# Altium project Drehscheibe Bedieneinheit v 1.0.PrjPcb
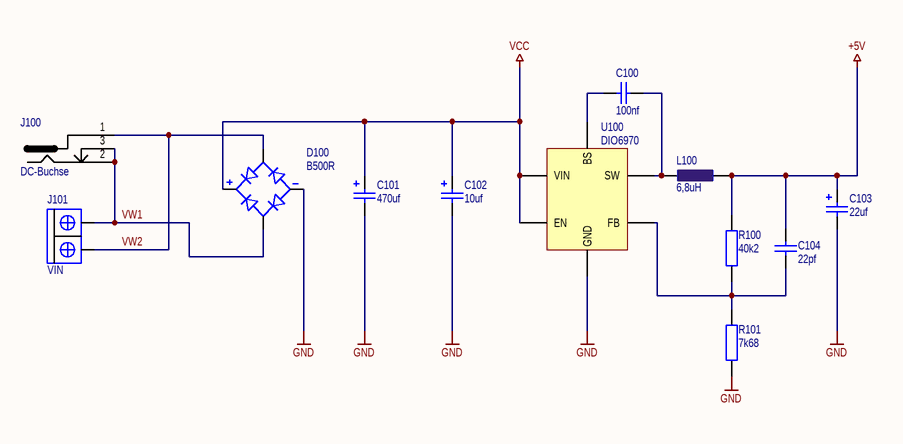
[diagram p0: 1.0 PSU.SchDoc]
City: Neustift-Innermanzing; Client: Wolfgang Paris, Gerhard Abraham; Company: PCSG; Country: Austria; Drawnby1: BRAL; Drawnby2: SONP; Email: office@pcsb.at; License: N/A; Number: 1; Phone: 02774/29452; Street: Hauptstraße 47; Title: Drehscheibe Bedieneinheit; Version: v1.0; web: www.pcsb.at; ZIP: A-3052
7 sheets, 71 parts. Net scope: global (net labels, ports and power ports of the same name join across sheets).
Board file: Bedieneinheit v1.0.PcbDoc
Sheets:
  1.0 PSU.SchDoc
  2.0 Microcontroller.SchDoc
  3.0 Display.SchDoc
  4.0 Steppermotor & Peripheral.SchDoc
  5.0 Demodulation.SchDoc
  6.0 Relais and Connector.SchDoc
  7.0 Bedieneinheit.SchDoc

## Sheet 1.0 PSU.SchDoc: Drehscheibe Bedieneinheit
size A4; SheetNumber: 1; SheetTotal: 7

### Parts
C100  100nf  [C_SMD_0805]
C101  470uf  [C_SMD_F-TYP]
C102  10uf  [C_SMD_C-TYP]
C103  22uf  [C_SMD_C-TYP]
C104  22pf  [C_SMD_0805]
D100  B500R  [D_THT_FBR-R]
J100  DC-Buchse  [J_THT_CUI_PJ-006A]
J101  VIN  [J_THT_Printklemme 2x]
L100  6,8uH  [L_SMD_BWVS00606045]
R100  40k2  [R_SMD_0805]
R101  7k68  [R_SMD_1206]
U100  DIO6970  [SOT23-6]

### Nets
+5V: C103.1 C104.1 L100.1 R100.2
GND: C101.2 C102.2 C103.2 D100.4(NEG) R101.1 U100.1(GND)
VCC: C101.1 C102.1 D100.1(POS) U100.3(VIN) U100.5(EN)
VW1: D100.3(AC2) J100.2 J100.3 J101.2
VW2: D100.2(AC1) J100.1 J101.1
NetC100_1: C100.1 U100.6(BS)
NetC100_2: C100.2 L100.2 U100.2(SW)
NetC104_2: C104.2 R100.1 R101.2 U100.4(FB)

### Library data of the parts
C100 C104 = C_SMD_KO: Kondensator SMD Universal, Keramik, Folie, usw.
C101-C103 = C_SMD_ELK: SMD Elektrolytkondensator
D100 = D_THT_Brückengleichrichter: Bruckengleichrichter
J100 = J_THT_Hohlstecker
J101 = J_THT_Printklemme 2x: Printklemme
L100 = L_SMD_Spule: Spule SMD
R100 R101 = R_SMD_Widerstand: Widerstand SMD
U100 = U_DIO6970: Buckconverter

## Sheet 2.0 Microcontroller.SchDoc: Drehscheibe Bedieneinheit
size A4; SheetNumber: 2; SheetTotal: 7
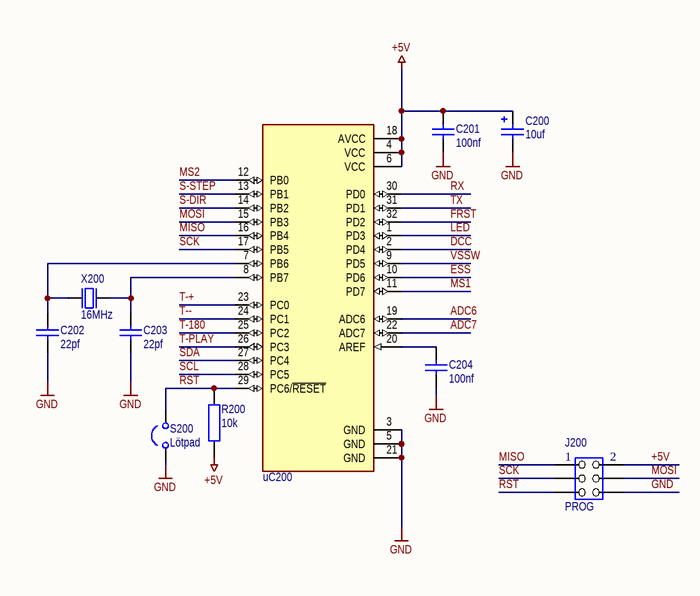
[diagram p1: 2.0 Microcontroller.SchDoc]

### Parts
C200  10uf  [C_SMD_C-TYP]
C201  100nf  [C_SMD_0805]
C202  22pf  [C_SMD_0805]
C203  22pf  [C_SMD_0805]
C204  100nf  [C_SMD_0805]
J200  PROG  [J_2x3]
R200  10k  [R_SMD_0805]
S200  Lötpad  [S_SMD_Pad-NO]
uC200  ATMega328(p)-AU  [TQFP-32]  (value not drawn)
X200  16MHz  [X_SMD_XTAL]

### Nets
+5V: C200.1 C201.1 J200.2 R200.1 uC200.4(VCC) uC200.6(VCC) uC200.18(AVCC)
GND: C200.2 C201.2 C202.2 C203.2 C204.2 J200.6 S200.1 uC200.3(GND) uC200.5(GND) uC200.21(GND)
ADC6: uC200.19(ADC6)
ADC7: uC200.22(ADC7)
DCC: uC200.2(PD4)
ESS: uC200.10(PD6)
FRST: uC200.32(PD2)
LED: uC200.1(PD3)
MISO: J200.1 uC200.16(PB4)
MOSI: J200.4 uC200.15(PB3)
MS1: uC200.11(PD7)
MS2: uC200.12(PB0)
RST: J200.5 R200.2 S200.2 uC200.29(PC6/~{RESET})
RX: uC200.30(PD0)
S-DIR: uC200.14(PB2)
S-STEP: uC200.13(PB1)
SCK: J200.3 uC200.17(PB5)
SCL: uC200.28(PC5)
SDA: uC200.27(PC4)
T-180: uC200.25(PC2)
T-+: uC200.23(PC0)
T--: uC200.24(PC1)
T-PLAY: uC200.26(PC3)
TX: uC200.31(PD1)
VSSW: uC200.9(PD5)
NetC202_1: C202.1 uC200.7(PB6) X200.1
NetC203_1: C203.1 uC200.8(PB7) X200.2
NetC204_1: C204.1 uC200.20(AREF)

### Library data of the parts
C200 = C_SMD_ELK: SMD Elektrolytkondensator
C201-C204 = C_SMD_KO: as C100 on sheet 1.0 PSU
J200 = J_THT_IDC 2x3: Stecker
R200 = R_SMD_Widerstand: Widerstand SMD
S200 = S_SMD_Jumper: Lötverbinder
uC200 = UC_ATMega328P-AU: Microcontroller
X200 = X_SMD_Quarz: Quarz SMD

## Sheet 3.0 Display.SchDoc: Drehscheibe Bedieneinheit
size A4; SheetNumber: 3; SheetTotal: 7
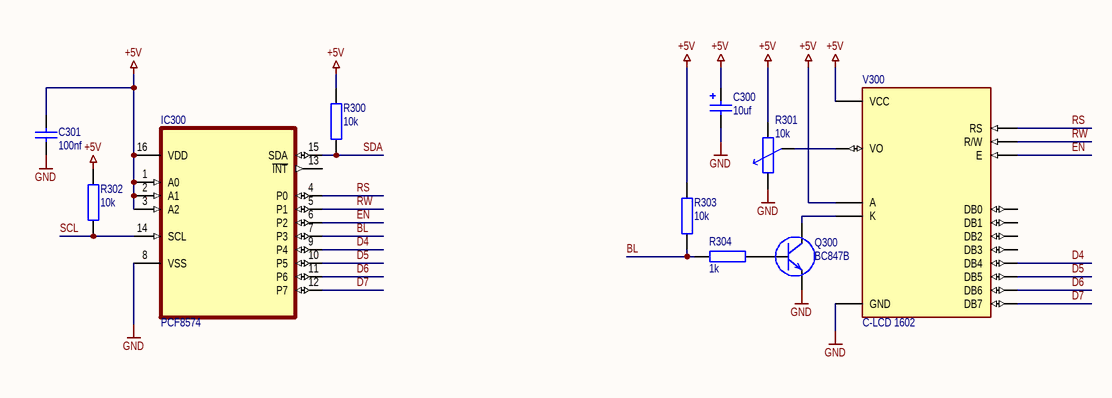
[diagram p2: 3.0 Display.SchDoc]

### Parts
C300  10uf  [C_SMD_C-TYP]
C301  100nf  [C_SMD_0805]
IC300  PCF8574  [SO-16]
Q300  BC847B  [SOT-23]
R300  10k  [R_SMD_0805]
R301  10k  [R_THT_POT-TP-.2/.1]
R302  10k  [R_SMD_0805]
R303  10k  [R_SMD_0805]
R304  1k  [R_SMD_0805]
V300  C-LCD 1602  [V_MODULE_LCD-16X2]

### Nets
+5V: C300.1 C301.1 IC300.1(A0) IC300.2(A1) IC300.3(A2) IC300.16(VDD) R300.2 R301.1 R302.2 R303.2 V300.2(VCC) V300.15(A)
GND: C300.2 C301.2 IC300.8(VSS) Q300.2(E) R301.2 V300.1(GND)
BL: IC300.7(P3) R303.1 R304.1
D4: IC300.9(P4) V300.11(DB4)
D5: IC300.10(P5) V300.12(DB5)
D6: IC300.11(P6) V300.13(DB6)
D7: IC300.12(P7) V300.14(DB7)
EN: IC300.6(P2) V300.6(E)
RS: IC300.4(P0) V300.4(RS)
RW: IC300.5(P1) V300.5(R/W)
SCL: IC300.14(SCL) R302.1
SDA: IC300.15(SDA) R300.1
NetQ300_1: Q300.1(B) R304.2
NetQ300_3: Q300.3(C) V300.16(K)
NetR301_3: R301.3 V300.3(VO)

Not connected (* = marked no-connect by the designer): IC300 13(~{INT}); V300 7(DB0) 8(DB1) 9(DB2) 10(DB3)

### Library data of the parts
C300 = C_SMD_ELK: SMD Elektrolytkondensator
C301 = C_SMD_KO: as C100 on sheet 1.0 PSU
IC300 = IC_PCF8574: I/O Expander
Q300 = Q_SMD_NPN: NPN Transistor
R300 R302-R304 = R_SMD_Widerstand: Widerstand SMD
R301 = R_THT_Potentiometer: Potentiometer; Set Position: 0.5
V300 = V_C-LCD-1602: LC-Display; MF: Gravitech; MP: LCD-16X2

## Sheet 4.0 Steppermotor & Peripheral.SchDoc: Drehscheibe Bedieneinheit
size A4; SheetNumber: 4; SheetTotal: 7
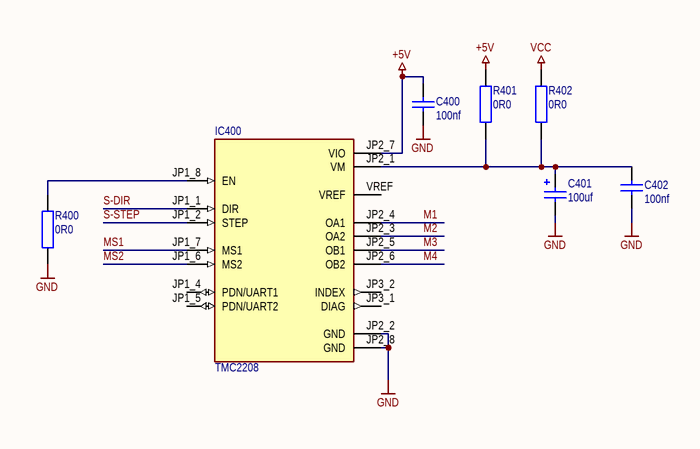
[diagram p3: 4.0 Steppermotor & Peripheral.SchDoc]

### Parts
C400  100nf  [C_SMD_0805]
C401  100uf  [C_SMD_D-TYP]
C402  100nf  [C_SMD_0805]
IC400  TMC2208  [IC_TMC2208]
R400  0R0  [R_SMD_0805]
R401  0R0  [R_SMD_0603]
R402  0R0  [R_SMD_0603]

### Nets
+5V: C400.1 IC400.JP2_7(VIO) R401.2
GND: C400.2 C401.2 C402.2 IC400.JP2_2(GND) IC400.JP2_8(GND) R400.1
VCC: R402.2
M1: IC400.JP2_4(OA1)
M2: IC400.JP2_3(OA2)
M3: IC400.JP2_5(OB1)
M4: IC400.JP2_6(OB2)
MS1: IC400.JP1_7(MS1)
MS2: IC400.JP1_6(MS2)
S-DIR: IC400.JP1_1(DIR)
S-STEP: IC400.JP1_2(STEP)
NetC401_1: C401.1 C402.1 IC400.JP2_1(VM) R401.1 R402.1
NetIC400_JP1_8: IC400.JP1_8(EN) R400.2

Not connected (* = marked no-connect by the designer): IC400 JP1_4(PDN/UART1) JP1_5(PDN/UART2) JP3_1(DIAG) JP3_2(INDEX) VREF

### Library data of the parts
C400 C402 = C_SMD_KO: as C100 on sheet 1.0 PSU
C401 = C_SMD_ELK: SMD Elektrolytkondensator
IC400 = IC_TMC2208: Schrittmotortreiber
R400-R402 = R_SMD_Widerstand: Widerstand SMD

## Sheet 5.0 Demodulation.SchDoc: Drehscheibe Bedieneinheit
size A4; SheetNumber: 5; SheetTotal: 7
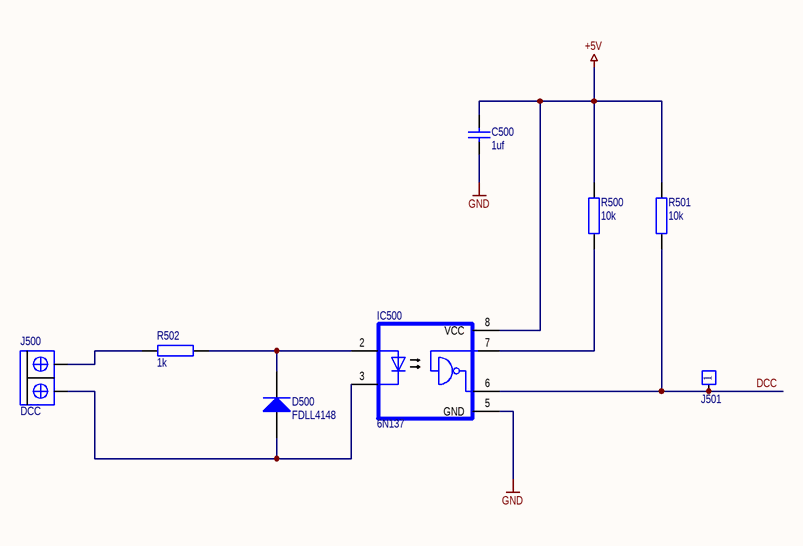
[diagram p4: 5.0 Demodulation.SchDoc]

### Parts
C500  1uf  [C_SMD_0805]
D500  FDLL4148  [D_SMD_1206]
IC500  6N137  [DIP-8]
J500  DCC  [J_THT_Printklemme 2x]
J501  #Wert  [SIP-1]  (value not drawn)
R500  10k  [R_SMD_0805]
R501  10k  [R_SMD_0805]
R502  1k  [R_SMD_0805]

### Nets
+5V: C500.1 IC500.8(VCC) R500.2 R501.2
GND: C500.2 IC500.5(GND)
DCC: IC500.6(VO) J501.1 R501.1
NetD500_1: D500.1(A) IC500.3(LED-) J500.1
NetD500_2: D500.2(K) IC500.2(LED+) R502.2
NetIC500_7: IC500.7(VE) R500.1
NetJ500_2: J500.2 R502.1

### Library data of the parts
C500 = C_SMD_KO: as C100 on sheet 1.0 PSU
D500 = D_SMD_Silizium: Diode SMD Silizium; Spannung For.: 0,7V
IC500 = IC_6N137: Optokoppler
J500 = J_THT_Printklemme 2x: Printklemme
J501 = J_THT_CON1: Stecker
R500-R502 = R_SMD_Widerstand: Widerstand SMD

## Sheet 6.0 Relais and Connector.SchDoc: Drehscheibe Bedieneinheit
size A4; SheetNumber: 6; SheetTotal: 7
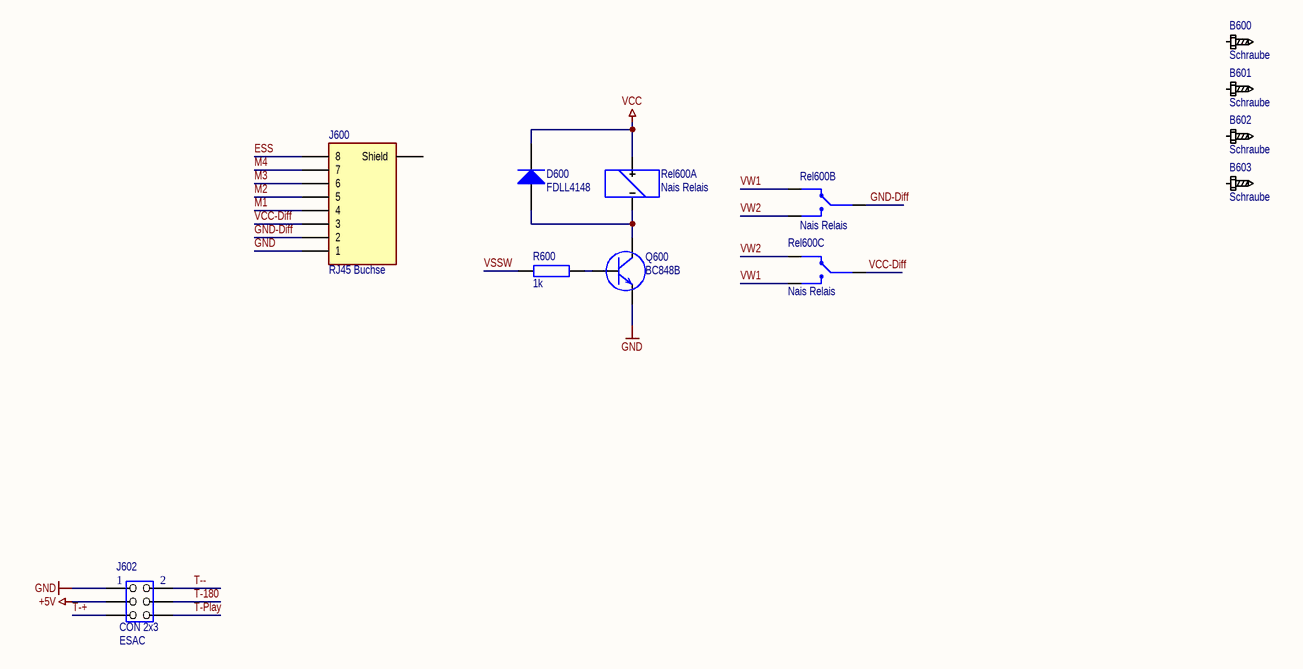
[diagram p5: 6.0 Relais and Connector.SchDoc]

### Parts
B600  Schraube  [B_Schraube-M3]
B601  Schraube  [B_Schraube-M3]
B602  Schraube  [B_Schraube-M3]
B603  Schraube  [B_Schraube-M3]
D600  FDLL4148  [D_SMD_1206]
J600  RJ45 Buchse  [J_TE-RJ45-8L-B]
J602  CON 2x3  Use: ESAC  [J_2x3]
Q600  BC848B  [SOT-23]
R600  1k  [R_SMD_0805]
Rel600  Nais Relais  [Rel_THT_Nais]  (parts A,B,C of 3)

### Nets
+5V: J602.3
GND: J600.1 J602.1 Q600.2(E)
VCC: D600.2(K) Rel600.5
ESS: J600.8
GND-Diff: J600.2 Rel600.3
M1: J600.4
M2: J600.5
M3: J600.6
M4: J600.7
T-180: J602.4
T-+: J602.5
T--: J602.2
T-PLAY: J602.6
VCC-Diff: J600.3 Rel600.6
VSSW: R600.1
VW1: Rel600.2 Rel600.8
VW2: Rel600.1 Rel600.7
NetD600_1: D600.1(A) Q600.3(C) Rel600.4
NetQ600_1: Q600.1(B) R600.2

Not connected (* = marked no-connect by the designer): B600 1(PAD); B601 1(PAD); B602 1(PAD); B603 1(PAD); J600 MP(Shield)

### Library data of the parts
B600-B603 = B_Schraube: Schraubenloch für M3 Schrauben
D600 = D_SMD_Silizium: Diode SMD Silizium; Spannung For.: 0,7V
J600 = J_RJ45: Connector
J602 = J_THT_IDC 2x3: Stecker
Q600 = Q_SMD_NPN: NPN Transistor
R600 = R_SMD_Widerstand: Widerstand SMD
Rel600 = Rel_THT_Nais: Nais DS2Y-S-DC12V

## Sheet 7.0 Bedieneinheit.SchDoc: Drehscheibe Bedieneinheit
size A4; SheetNumber: 7; SheetTotal: 7
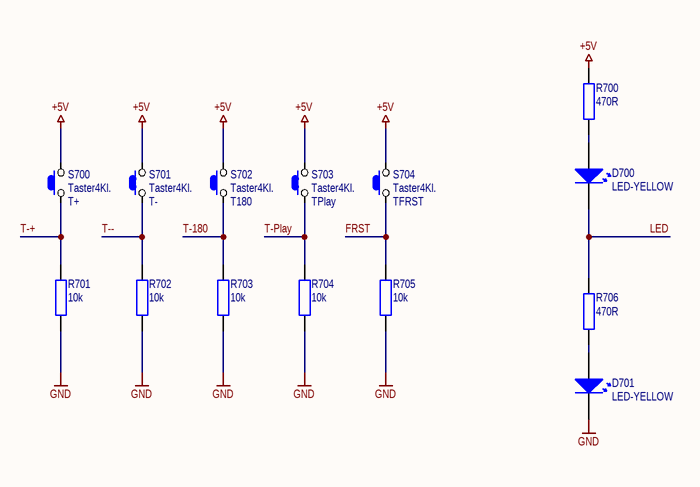
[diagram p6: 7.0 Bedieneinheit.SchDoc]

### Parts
D700  LED-YELLOW  [D_THT_LED-5]
D701  LED-YELLOW  [D_THT_LED-5]
R700  470R  [R_SMD_0805]
R701  10k  [R_SMD_0805]
R702  10k  [R_SMD_0805]
R703  10k  [R_SMD_0805]
R704  10k  [R_SMD_0805]
R705  10k  [R_SMD_0805]
R706  470R  [R_SMD_0805]
S700  Taster4Kl.  Use: T+  [S_THT_Taster4kl.]
S701  Taster4Kl.  Use: T-  [S_THT_Taster4kl.]
S702  Taster4Kl.  Use: T180  [S_THT_Taster4kl.]
S703  Taster4Kl.  Use: TPlay  [S_THT_Taster4kl.]
S704  Taster4Kl.  Use: TFRST  [S_THT_Taster4kl.]

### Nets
+5V: R700.2 S700.2 S701.2 S702.2 S703.2 S704.2
GND: D701.2(K) R701.1 R702.1 R703.1 R704.1 R705.1
FRST: R705.2 S704.1
LED: D700.2(K) R706.2
T-180: R703.2 S702.1
T-+: R701.2 S700.1
T--: R702.2 S701.1
T-PLAY: R704.2 S703.1
NetD700_1: D700.1(A) R700.1
NetD701_1: D701.1(A) R706.1

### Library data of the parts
D700 D701 = D_THT_LED: Diode THT LED; Spannung For.: 1,8V-3,6V
R700-R706 = R_SMD_Widerstand: Widerstand SMD
S700-S704 = S_THT_Taster: Taster

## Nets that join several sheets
+5V: 1.0 PSU (C103.1 C104.1 L100.1 R100.2), 2.0 Microcontroller (7 pins), 3.0 Display (12 pins), 4.0 Steppermotor & Peripheral (C400.1 IC400.JP2_7 R401.2), 5.0 Demodulation (C500.1 IC500.8 R500.2 R501.2), 6.0 Relais and Connector (J602.3), 7.0 Bedieneinheit (6 pins)
GND: 1.0 PSU (6 pins), 2.0 Microcontroller (10 pins), 3.0 Display (6 pins), 4.0 Steppermotor & Peripheral (6 pins), 5.0 Demodulation (C500.2 IC500.5), 6.0 Relais and Connector (J600.1 J602.1 Q600.2), 7.0 Bedieneinheit (6 pins)
VCC: 1.0 PSU (5 pins), 4.0 Steppermotor & Peripheral (R402.2), 6.0 Relais and Connector (D600.2 Rel600.5)
DCC: 2.0 Microcontroller (uC200.2), 5.0 Demodulation (IC500.6 J501.1 R501.1)
ESS: 2.0 Microcontroller (uC200.10), 6.0 Relais and Connector (J600.8)
FRST: 2.0 Microcontroller (uC200.32), 7.0 Bedieneinheit (R705.2 S704.1)
LED: 2.0 Microcontroller (uC200.1), 7.0 Bedieneinheit (D700.2 R706.2)
M1: 4.0 Steppermotor & Peripheral (IC400.JP2_4), 6.0 Relais and Connector (J600.4)
M2: 4.0 Steppermotor & Peripheral (IC400.JP2_3), 6.0 Relais and Connector (J600.5)
M3: 4.0 Steppermotor & Peripheral (IC400.JP2_5), 6.0 Relais and Connector (J600.6)
M4: 4.0 Steppermotor & Peripheral (IC400.JP2_6), 6.0 Relais and Connector (J600.7)
MS1: 2.0 Microcontroller (uC200.11), 4.0 Steppermotor & Peripheral (IC400.JP1_7)
MS2: 2.0 Microcontroller (uC200.12), 4.0 Steppermotor & Peripheral (IC400.JP1_6)
S-DIR: 2.0 Microcontroller (uC200.14), 4.0 Steppermotor & Peripheral (IC400.JP1_1)
S-STEP: 2.0 Microcontroller (uC200.13), 4.0 Steppermotor & Peripheral (IC400.JP1_2)
SCL: 2.0 Microcontroller (uC200.28), 3.0 Display (IC300.14 R302.1)
SDA: 2.0 Microcontroller (uC200.27), 3.0 Display (IC300.15 R300.1)
T-180: 2.0 Microcontroller (uC200.25), 6.0 Relais and Connector (J602.4), 7.0 Bedieneinheit (R703.2 S702.1)
T-+: 2.0 Microcontroller (uC200.23), 6.0 Relais and Connector (J602.5), 7.0 Bedieneinheit (R701.2 S700.1)
T--: 2.0 Microcontroller (uC200.24), 6.0 Relais and Connector (J602.2), 7.0 Bedieneinheit (R702.2 S701.1)
T-PLAY: 2.0 Microcontroller (uC200.26), 6.0 Relais and Connector (J602.6), 7.0 Bedieneinheit (R704.2 S703.1)
VSSW: 2.0 Microcontroller (uC200.9), 6.0 Relais and Connector (R600.1)
VW1: 1.0 PSU (D100.3 J100.2 J100.3 J101.2), 6.0 Relais and Connector (Rel600.2 Rel600.8)
VW2: 1.0 PSU (D100.2 J100.1 J101.1), 6.0 Relais and Connector (Rel600.1 Rel600.7)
